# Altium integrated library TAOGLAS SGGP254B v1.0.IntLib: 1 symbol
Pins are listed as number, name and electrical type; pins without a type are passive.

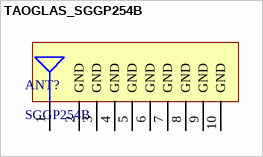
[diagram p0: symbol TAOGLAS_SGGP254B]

## TAOGLAS_SGGP254B
designator ANT?, comment SGGP254B
GPS/GLONASS/GALILEO/BEIDOU 25*25*4mm Ceramic Patch SMD Antenna; ComponentLibStatus: Created; MFG: Taoglas; Temp_High: +85C; Temp_Low: -40C
footprint TAOGLAS_SGGP254B (GPS/GLONASS/GALILEO/BEIDOU 25*25*4mm Ceramic Patch SMD Antenna)
pins: 1 RF FEED, 2 GND, 3 GND, 4 GND, 5 GND, 6 GND, 7 GND, 8 GND, 9 GND, 10 GND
